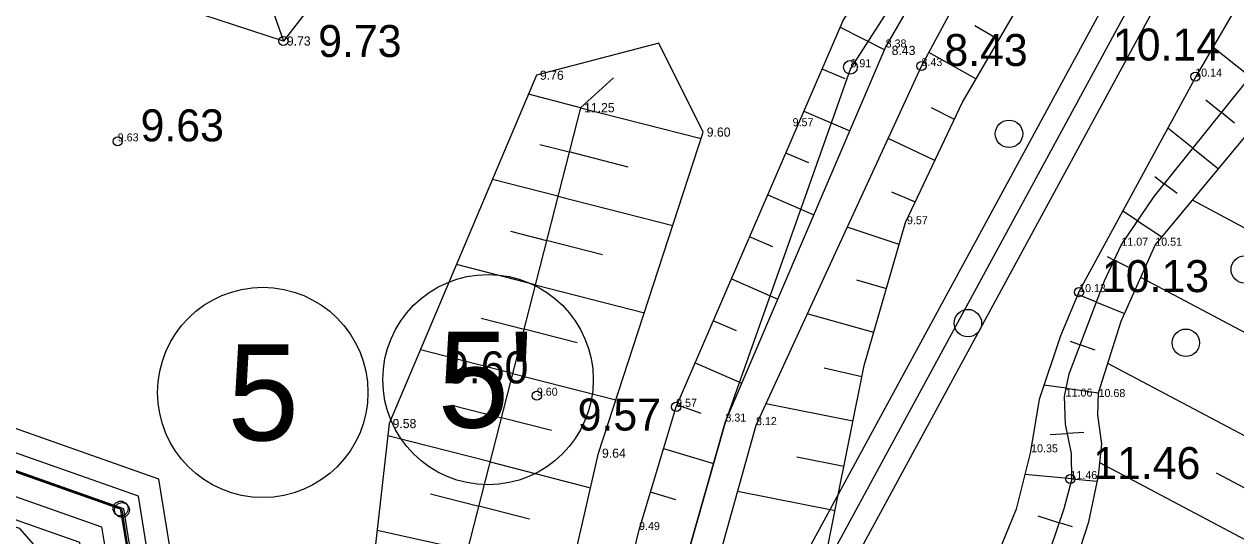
# Model space of a CAD drawing. Extents: x 433497 to 434382, y 6534486 to 6534993.
# Drawn here: x 434123.5 to 434176.5, y 6534854.4 to 6534876.8 of the extents above; entities that cross this region are included whole.
import ezdxf

# ---------------------------------------------------------------- set-up
doc = ezdxf.new("R2010")
doc.units = 0
for name, color, linetype in [('Default', 7, 'Continuous'), ('HALJASTUS', 7, 'Continuous'), ('kataster', 7, 'Continuous'), ('KORGUS', 7, 'Continuous'), ('KORGUS-EH2000', 7, 'Continuous'), ('MAAMUDEL-EH2000', 7, 'Continuous'), ('MOOTKORG-EH2000', 7, 'Continuous'), ('PIIR', 7, 'Continuous'), ('RELJEEF', 7, 'Continuous'), ('Täide', 7, 'Continuous'), ('VEEKOGU', 7, 'Continuous')]:
    doc.layers.add(name, color=color, linetype=linetype)

msp = doc.modelspace()

# ---------------------------------------------------------------- linework, layer by layer
at = {"layer": 'Default'}
msp.add_lwpolyline([(433617.12, 6534791.025), (433632.75, 6534606.045), (434137.38, 6534796.515), (434127.69, 6534855.6), (433968.21, 6534911.925), (433942.38, 6534904.035), (433920.99, 6534907.275)], close=True, dxfattribs=at)
msp.add_lwpolyline([(433617.12, 6534791.025), (433632.75, 6534606.045), (434137.38, 6534796.515), (434127.69, 6534855.6), (433968.21, 6534911.925), (433942.38, 6534904.035), (433920.99, 6534907.275)], close=True, dxfattribs=at)
msp.add_lwpolyline([(433617.12, 6534791.025), (433632.75, 6534606.045), (434137.38, 6534796.515), (434127.69, 6534855.6), (433968.21, 6534911.925), (433942.38, 6534904.035), (433920.99, 6534907.275)], close=True, dxfattribs=at)
at = {"layer": 'HALJASTUS'}
for centre in [(434166.544, 6534871.996), (434176.855, 6534866.059), (434164.747, 6534863.716), (434174.278, 6534862.856)]:
    msp.add_circle(centre, 0.6, dxfattribs=at)
at = {"layer": 'kataster'}
msp.add_lwpolyline([(433617.102, 6534791.002), (433632.769, 6534606.029), (434137.446, 6534796.469), (434127.827, 6534855.589), (433950.026, 6534918.39)], close=True, dxfattribs=at)
at = {"layer": 'KORGUS'}
msp.add_circle((434134.812, 6534876.057), 0.2, dxfattribs=at)
at = {"layer": 'KORGUS-EH2000'}
for centre in [(434162.718, 6534874.963), (434174.69, 6534874.5), (434127.565, 6534871.665), (434169.61, 6534865.07), (434145.894, 6534860.537), (434151.986, 6534860.051), (434169.23, 6534856.89)]:
    msp.add_circle(centre, 0.2, dxfattribs=at)
at = {"layer": 'PIIR'}
for points in [[(434138.342, 6534801.592), (434129.36, 6534856.88), (433968.248, 6534913.871)], [(433632.021, 6534604.835), (434138.248, 6534795.936), (434128.468, 6534856.135), (433968.226, 6534912.818), (433942.33, 6534904.85), (433920.952, 6534908.165), (433616.327, 6534791.524), (433632.021, 6534604.835)], [(433632.732, 6534605.959), (434137.353, 6534796.454), (434127.754, 6534855.539), (433968.208, 6534911.976), (433942.39, 6534904.031), (433921.04, 6534907.341), (433617.174, 6534790.992), (433632.732, 6534605.959)], [(434137.312, 6534801.699), (434156.44, 6534851.34), (434184.392, 6534902.877)], [(434138.342, 6534801.592), (434157.35, 6534850.92), (434185.271, 6534902.4)], [(434138.358, 6534798.853), (434158.26, 6534850.5), (434186.15, 6534901.923)]]:
    msp.add_lwpolyline(points, dxfattribs=at)
for points in [[(433618.234, 6534790.327), (433921.149, 6534906.313), (433942.464, 6534903.008), (433968.187, 6534910.923), (434126.862, 6534854.794), (434136.235, 6534797.101), (433633.617, 6534607.362)], [(433619.24, 6534789.695), (433634.52, 6534608.851), (434135.141, 6534797.808), (434125.908, 6534854.108), (433968.165, 6534909.82), (433942.53, 6534901.99), (433921.212, 6534905.219)], [(433619.24, 6534789.695), (433634.52, 6534608.851), (434135.141, 6534797.808), (434125.908, 6534854.108), (433968.165, 6534909.82), (433942.53, 6534901.99), (433921.212, 6534905.219)]]:
    msp.add_lwpolyline(points, close=True, dxfattribs=at)
for centre, radius in [((434143.76, 6534861.241), 4.6), ((434133.909, 6534860.68), 4.6), ((434127.69, 6534855.6), 0.325), ((434127.754, 6534855.539), 0.325)]:
    msp.add_circle(centre, radius, dxfattribs=at)
at = {"layer": 'RELJEEF'}
for p, q in [((434132.854, 6534881.701), (434134.812, 6534876.057)), ((434159.164, 6534876.664), (434161.107, 6534875.673)), ((434165.054, 6534876.735), (434166.104, 6534876.122)), ((434165.095, 6534874.395), (434163.034, 6534875.55)), ((434177.092, 6534874.486), (434175.463, 6534875.788)), ((434147.81, 6534873.14), (434149.247, 6534874.444)), ((434159.372, 6534874.395), (434158.37, 6534874.828)), ((434147.81, 6534873.14), (434145.526, 6534873.724)), ((434175.152, 6534873.479), (434175.84, 6534872.927)), ((434147.81, 6534873.14), (434153.084, 6534871.791)), ((434157.577, 6534872.992), (434159.587, 6534872.123)), ((434163.134, 6534873.147), (434164.15, 6534872.634)), ((434176.413, 6534872.466), (434175.84, 6534872.927)), ((434163.295, 6534870.826), (434161.257, 6534871.791)), ((434174.588, 6534871.367), (434173.492, 6534872.246)), ((434146.027, 6534871.532), (434147.315, 6534871.202)), ((434174.588, 6534871.367), (434175.71, 6534870.466)), ((434149.888, 6534870.544), (434147.315, 6534871.202)), ((434157.792, 6534870.72), (434156.784, 6534871.156)), ((434146.819, 6534869.265), (434143.951, 6534869.998)), ((434172.922, 6534870.122), (434173.336, 6534869.807)), ((434173.896, 6534869.381), (434173.336, 6534869.807)), ((434146.819, 6534869.265), (434151.841, 6534867.98)), ((434155.991, 6534869.32), (434158.013, 6534868.446)), ((434161.411, 6534869.455), (434162.44, 6534869.018)), ((434172.167, 6534868.186), (434171.517, 6534868.614)), ((434185.463, 6534863.257), (434174.571, 6534869.094)), ((434172.167, 6534868.186), (434173.235, 6534867.484)), ((434144.743, 6534867.731), (434146.324, 6534867.327)), ((434161.736, 6534867.153), (434159.468, 6534867.907)), ((434148.772, 6534866.701), (434146.324, 6534867.327)), ((434156.212, 6534867.045), (434155.197, 6534867.484)), ((434170.834, 6534866.632), (434171.144, 6534866.474)), ((434145.828, 6534865.389), (434142.375, 6534866.272)), ((434171.756, 6534866.164), (434171.144, 6534866.474)), ((434154.404, 6534865.648), (434156.44, 6534864.768)), ((434159.881, 6534865.607), (434161.181, 6534865.232)), ((434183.589, 6534859.723), (434172.304, 6534865.709)), ((434145.828, 6534865.389), (434150.599, 6534864.169)), ((434170.364, 6534864.634), (434169.553, 6534864.96)), ((434170.364, 6534864.634), (434171.6, 6534864.137)), ((434143.46, 6534863.931), (434145.333, 6534863.452)), ((434160.627, 6534863.31), (434157.722, 6534864.116)), ((434147.655, 6534862.858), (434145.333, 6534863.452)), ((434154.632, 6534863.371), (434153.611, 6534863.812)), ((434169.214, 6534862.919), (434169.653, 6534862.765)), ((434144.837, 6534861.514), (434140.8, 6534862.546)), ((434170.313, 6534862.533), (434169.653, 6534862.765)), ((434152.818, 6534861.976), (434154.866, 6534861.091)), ((434158.464, 6534861.763), (434160.112, 6534861.379)), ((434181.714, 6534856.19), (434170.86, 6534861.947)), ((434144.837, 6534861.514), (434149.356, 6534860.358)), ((434169.04, 6534860.867), (434168.073, 6534861.005)), ((434169.04, 6534860.867), (434170.454, 6534860.665)), ((434142.177, 6534860.13), (434144.342, 6534859.576)), ((434153.078, 6534859.752), (434152.024, 6534860.14)), ((434159.72, 6534859.418), (434155.909, 6534860.18)), ((434146.538, 6534859.015), (434144.342, 6534859.576)), ((434143.846, 6534857.639), (434139.374, 6534858.782)), ((434168.348, 6534858.836), (434169.096, 6534858.884)), ((434169.814, 6534858.93), (434169.096, 6534858.884)), ((434151.437, 6534858.229), (434153.621, 6534857.565)), ((434143.846, 6534857.639), (434148.248, 6534856.513)), ((434157.269, 6534857.868), (434159.327, 6534857.457)), ((434179.84, 6534852.656), (434170.518, 6534857.601)), ((434169.295, 6534856.902), (434167.241, 6534857.085)), ((434175.605, 6534857.166), (434180.777, 6534854.423)), ((434169.295, 6534856.902), (434170.407, 6534856.803)), ((434141.249, 6534856.239), (434143.351, 6534855.701)), ((434151.969, 6534855.984), (434150.861, 6534856.314)), ((434158.935, 6534855.495), (434154.671, 6534856.348)), ((434145.575, 6534855.132), (434143.351, 6534855.701)), ((434167.806, 6534855.28), (434168.748, 6534854.981)), ((434169.325, 6534854.798), (434168.748, 6534854.981)), ((434142.855, 6534853.763), (434138.905, 6534854.647))]:
    msp.add_line(p, q, dxfattribs=at)
for points in [[(434146.988, 6534822.533), (434142.84, 6534823.556), (434150.364, 6534854.663), (434151.986, 6534860.051), (434159.289, 6534876.954), (434168.982, 6534892.451), (434176.303, 6534903.68)], [(434145.026, 6534824.798), (434149.741, 6534843.917), (434154.144, 6534859.405), (434161.15, 6534875.774), (434169.455, 6534890.171), (434178.472, 6534903.261)], [(434145.026, 6534824.798), (434146.573, 6534825.031), (434151.094, 6534843.526), (434155.48, 6534859.249), (434162.718, 6534874.963), (434170.742, 6534889.851), (434180.097, 6534902.569)], [(434157.71, 6534847.595), (434158.32, 6534852.418), (434160.207, 6534861.853), (434162.014, 6534868.117), (434164.505, 6534873.384), (434174.095, 6534889.798), (434181.01, 6534899.801)], [(434129.779, 6534889.923), (434132.268, 6534892.372), (434137.015, 6534892.274), (434137.95, 6534886.14), (434136.77, 6534878.6), (434134.812, 6534876.057), (434129.81, 6534877.69), (434129.28, 6534881.33), (434129.24, 6534886.58), (434129.779, 6534889.923)], [(434177.736, 6534879.703), (434174.757, 6534874.572), (434169.627, 6534865.138), (434168.803, 6534863.153), (434167.859, 6534860.375), (434167.475, 6534858.022), (434166.863, 6534855.579), (434165.489, 6534852.229), (434163.666, 6534848.215), (434162.958, 6534846.721), (434162.51, 6534845.278), (434162.041, 6534843.524), (434161.517, 6534840.147), (434159.697, 6534830.713), (434158.687, 6534827.511), (434156.433, 6534820.225)], [(434126.192, 6534811.695), (434132.1, 6534807.95), (434137.84, 6534821.85), (434145.35, 6534843.91), (434148.595, 6534858.023), (434153.175, 6534872.071), (434151.226, 6534875.962), (434145.88, 6534874.56)], [(434168.357, 6534853.843), (434168.96, 6534855.599), (434169.296, 6534856.863), (434169.274, 6534858.01), (434169.012, 6534859.294), (434168.965, 6534860.504), (434169.17, 6534861.496), (434170.716, 6534865.558), (434171.447, 6534867.124), (434172.891, 6534869.253), (434177.582, 6534875.097)], [(434145.88, 6534874.56), (434139.435, 6534859.319), (434137.93, 6534846.04), (434135.82, 6534833.16), (434132.11, 6534821.2), (434126.192, 6534811.695)], [(434169.13, 6534852.229), (434170.034, 6534855.022), (434170.454, 6534857.028), (434170.611, 6534858.429), (434170.428, 6534859.687), (434170.454, 6534860.67), (434171.45, 6534863.802), (434172.937, 6534867.124), (434178.552, 6534873.892)], [(434147.81, 6534873.14), (434142.66, 6534853), (434140.649, 6534839.695), (434136.95, 6534825.97), (434131, 6534814.2)]]:
    msp.add_lwpolyline(points, dxfattribs=at)
at = {"layer": 'Täide'}
msp.add_lwpolyline([(434053.953, 6534766.741), (434062.043, 6534770.897), (434076.601, 6534775.79), (434083.107, 6534779.636), (434100.67, 6534785.732), (434110.817, 6534789.511), (434130.115, 6534796.22), (434132.899, 6534799.258), (434133.017, 6534809.88), (434125.182, 6534852.548), (434123.278, 6534854.722), (434098.113, 6534862.108), (434062.901, 6534875.407), (434022.093, 6534888.443), (434021.059, 6534887.256), (434037.893, 6534864.165), (434021.392, 6534791.18), (434023.3, 6534781.148), (434025.663, 6534773.898), (434039.607, 6534770.357), (434045.083, 6534767.989), (434045.714, 6534765.502), (434044.882, 6534761.539)], dxfattribs=at)
at = {"layer": 'VEEKOGU'}
msp.add_lwpolyline([(434169.455, 6534890.171), (434159.61, 6534874.859), (434154.144, 6534859.405), (434149.741, 6534843.917), (434145.026, 6534824.798), (434146.573, 6534825.031), (434151.094, 6534843.526), (434155.48, 6534859.249), (434162.718, 6534874.963), (434170.742, 6534889.851), (434180.097, 6534902.569)], dxfattribs=at)
msp.add_circle((434159.61, 6534874.909), 0.3, dxfattribs=at)

# ---------------------------------------------------------------- texts
at = {"layer": 'KORGUS-EH2000'}
for s, p in [(' 9.73', (434135.812, 6534875.357)), ('10.14', (434171.089, 6534875.202)), ('8.43', (434163.718, 6534874.963)), ('9.63', (434128.565, 6534871.665)), ('10.13', (434170.61, 6534865.07)), ('9.60', (434141.879, 6534861.076)), ('9.57', (434147.681, 6534859.015)), ('11.46', (434170.23, 6534856.89))]:
    msp.add_text(s, height=1.4, dxfattribs=at).set_placement(p)
at = {"layer": 'MAAMUDEL-EH2000'}
for s, p in [(' 9.73', (434134.812, 6534875.857)), (' 8.43', (434161.264, 6534875.445)), (' 9.76', (434145.88, 6534874.36)), (' 11.25', (434147.81, 6534872.94)), (' 9.60', (434153.175, 6534871.871)), (' 9.58', (434139.435, 6534859.119)), (' 9.64', (434148.595, 6534857.823))]:
    msp.add_text(s, height=0.4, dxfattribs=at).set_placement(p)
at = {"layer": 'MOOTKORG-EH2000'}
for s, p in [('8.38', (434161.15, 6534875.774)), ('8.91', (434159.61, 6534874.909)), ('8.43', (434162.718, 6534874.963)), ('10.14', (434174.69, 6534874.5)), ('9.57', (434157.08, 6534872.33)), ('9.63', (434127.565, 6534871.665)), ('9.57', (434162.08, 6534868.04)), ('11.07', (434171.46, 6534867.1)), ('10.51', (434172.94, 6534867.1)), ('10.13', (434169.61, 6534865.07)), ('9.60', (434145.894, 6534860.537)), ('11.06', (434169.02, 6534860.5)), ('10.68', (434170.46, 6534860.48)), ('9.57', (434151.986, 6534860.051)), ('8.31', (434154.144, 6534859.405)), ('8.12', (434155.48, 6534859.249)), ('10.35', (434167.51, 6534858.06)), ('11.46', (434169.23, 6534856.89)), ('9.49', (434150.364, 6534854.663))]:
    msp.add_text(s, height=0.35, dxfattribs=at).set_placement(p)
at = {"layer": 'PIIR'}
for s, p in [("5'", (434141.559, 6534859.141)), ('5', (434132.366, 6534858.58))]:
    msp.add_text(s, height=4.2, dxfattribs=at).set_placement(p)

doc.saveas('drawing.dxf')
